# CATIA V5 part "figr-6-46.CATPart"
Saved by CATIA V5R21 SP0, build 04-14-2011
Part number: Part1
Bounding box of the stored display mesh (mm): x -26.811 to 26.811, y -47.298 to 47.298, z 0 to 31.431
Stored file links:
  D:\CATIA V5R21 E-RESOURCES\CATIA-V5R21\catia-v5r21-prt\c06-catia-v5r21-prt\c06-catia-v5r21-figr-6-46.CATPart
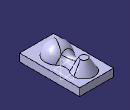
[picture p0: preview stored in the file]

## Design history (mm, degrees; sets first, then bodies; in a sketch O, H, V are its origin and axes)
Body1 (main body)
  Sketch1 on xy-plane, origin (0, 0, 0), H (1, 0, 0), V (0, 1, 0)
    line L1 (-26.8114, 47.2981) -> (26.8114, 47.2981)
    line L2 (26.8114, 47.2981) -> (26.8114, -47.2981)
    line L3 (26.8114, -47.2981) -> (-26.8114, -47.2981)
    line L4 (-26.8114, -47.2981) -> (-26.8114, 47.2981)
    axis line L5 (26.8114, -47.2981) -> (-26.8114, 47.2981)
    horizontal: L1 H, L3 H
    vertical: L2 V, L4 V
    coincidence: L5 O
    midpoint: L5 O
  Pad1: profile Sketch1, direction (0, 0, 1), length 12
  Sketch2 on yz-plane, origin (0, 0, 0), H (0, 1, 0), V (0, 0, 1)
    axis line L1 (-14.846, 35.4307) -> (-14.846, -5.9324)
    arc A1 centre (-14.846, 12.2093) radius 19.2216 from (-14.846, 31.431) to (-33.1926, 6.476) ccw
    point P3 (-14.846, 12.2093)
    point P4 (-14.846, 31.431)
    line L2 (-14.846, 31.431) -> (-14.846, 8.3996)
    line L3 (-14.846, 8.3996) -> (-33.1926, 6.476)
    vertical: L1 V, L2 V
    coincidence: P3 L1, P4 L1, A1 O
  Shaft1: profile Sketch2, axis Sketch2.L1, angle 360
  Sketch3 on face of Pad1, origin (0, 0, 12), H (1, 0, 0), V (0, 1, 0)
    circle A1 centre (0, 27.4246) radius 16.1543
    point P1 (0, 27.4246)
    coincidence: P1 V
  Pad2: profile Sketch3, direction (0, 0, 1), length 18
  Draft1: Angle 30, Neutral face of Pad1, PullDir face of Pad1, SupportToDraft face of Pad2
  FaceFillet1: Face1 face of Shaft1, Face2 face of Pad2, Radius 15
